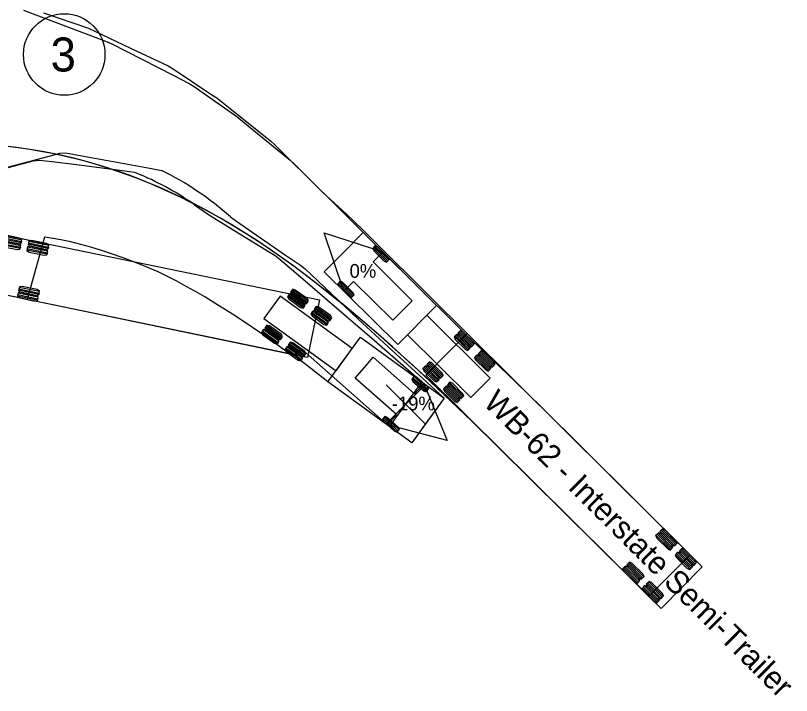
# Model space of a CAD drawing. Extents: x 1475900 to 1484331, y 375914 to 383395.
# Drawn here: x 1479059.2 to 1479171.7, y 379876.1 to 379974.6 of the extents above; entities that cross this region are included whole.
import ezdxf

# ---------------------------------------------------------------- set-up
doc = ezdxf.new("R2010")
doc.units = 0
doc.layers.add('0 (Construction)', color=7, linetype='Continuous')
doc.layers.add('Default', color=7, linetype='Continuous')

# ---------------------------------------------------------------- blocks, each defined once
blk = doc.blocks.new('ATRPTH_2')
at = {"layer": '0 (Construction)'}
blk.add_lwpolyline([(375840.717, 96487.897), (375840.359, 96487.536), (375838.916, 96488.967), (375838.559, 96488.607), (375837.832, 96490.759), (375839.99, 96490.049), (375839.632, 96489.688), (375841.074, 96488.257), (375840.717, 96487.897)], dxfattribs=at)
blk.add_circle((375828.26, 96497.315), 1.5, dxfattribs=at)
at = {"layer": 'Default'}
for points in [[(375850.233, 96476.932), (375844.254, 96482.859), (375843.255, 96483.836), (375842.499, 96484.564), (375841.737, 96485.285), (375841.097, 96485.879), (375840.448, 96486.466), (375839.926, 96486.929), (375839.396, 96487.387), (375838.86, 96487.839), (375838.045, 96488.503), (375837.501, 96488.93), (375837.082, 96489.248), (375836.66, 96489.561), (375836.098, 96489.961), (375835.531, 96490.347), (375834.953, 96490.721), (375834.513, 96490.991), (375834.07, 96491.253), (375833.471, 96491.586), (375833.172, 96491.745), (375832.87, 96491.899), (375832.563, 96492.049), (375831.941, 96492.34), (375831.478, 96492.542), (375831.021, 96492.727), (375830.552, 96492.903), (375829.912, 96493.122), (375829.433, 96493.269), (375829.113, 96493.362), (375828.629, 96493.488), (375828.304, 96493.566), (375827.815, 96493.671), (375827.324, 96493.763), (375826.995, 96493.817), (375826.668, 96493.866), (375826.173, 96493.928)], [(375827.498, 96498.848), (375829.15, 96498.284), (375830.705, 96497.543), (375832.088, 96496.895), (375832.273, 96496.784), (375833.694, 96495.836), (375833.873, 96495.718), (375834.369, 96495.323), (375835.861, 96494.135), (375836.015, 96493.993), (375837.775, 96492.252), (375838.651, 96491.438), (375839.253, 96490.863), (375839.846, 96490.281), (375851.754, 96478.465), (375850.233, 96476.932)], [(375849.782, 96477.38), (375844.185, 96482.927), (375843.153, 96483.935), (375842.268, 96484.786), (375841.535, 96485.476), (375840.942, 96486.023), (375840.344, 96486.563), (375839.746, 96487.089), (375839.145, 96487.604), (375838.535, 96488.111), (375838.072, 96488.485), (375837.615, 96488.846), (375837.172, 96489.186), (375836.721, 96489.521), (375836.264, 96489.85), (375835.801, 96490.171), (375835.336, 96490.481), (375834.885, 96490.77), (375834.427, 96491.051), (375833.961, 96491.322), (375833.489, 96491.585), (375833.016, 96491.834), (375832.549, 96492.067), (375832.234, 96492.216), (375831.755, 96492.431), (375831.269, 96492.635), (375830.789, 96492.823), (375830.309, 96492.997), (375829.822, 96493.159), (375829.33, 96493.308), (375828.843, 96493.442), (375828.515, 96493.523), (375828.018, 96493.635), (375827.516, 96493.735), (375827.009, 96493.821), (375826.5, 96493.894), (375825.988, 96493.953)], [(375826.762, 96498.95), (375829.168, 96498.042), (375829.776, 96497.81), (375829.984, 96497.725), (375832.273, 96496.554), (375832.858, 96496.252), (375833.042, 96496.135), (375834.616, 96495.035), (375835.107, 96494.634), (375836.581, 96493.423), (375836.737, 96493.277), (375843.048, 96487.019), (375844.022, 96486.096), (375844.876, 96485.271), (375845.844, 96484.324), (375847.312, 96482.873), (375851.303, 96478.912), (375849.782, 96477.38)], [(375839.269, 96490.765), (375841.973, 96488.081), (375840.542, 96486.639), (375837.837, 96489.322), (375838.553, 96490.043), (375839.269, 96490.765), (375839.269, 96490.765)], [(375839.63, 96490.191), (375840.135, 96489.69), (375840.171, 96489.726), (375839.666, 96490.227), (375839.702, 96490.263), (375840.207, 96489.762), (375840.219, 96489.775), (375840.179, 96489.861), (375839.801, 96490.237), (375839.714, 96490.275), (375839.618, 96490.179), (375839.658, 96490.093), (375840.036, 96489.717), (375840.123, 96489.678), (375840.219, 96489.775)], [(375838.342, 96488.893), (375838.847, 96488.392), (375838.883, 96488.428), (375838.378, 96488.929), (375838.414, 96488.965), (375838.918, 96488.464), (375838.93, 96488.476), (375838.891, 96488.563), (375838.512, 96488.939), (375838.426, 96488.977), (375838.33, 96488.881), (375838.369, 96488.795), (375838.748, 96488.419), (375838.835, 96488.38), (375838.93, 96488.476)], [(375840.9, 96486.999), (375843.226, 96484.691), (375843.941, 96485.412), (375841.615, 96487.72), (375840.9, 96486.999)], [(375842.767, 96487.078), (375843.272, 96486.577), (375843.308, 96486.613), (375842.803, 96487.114), (375842.839, 96487.15), (375843.344, 96486.649), (375843.356, 96486.661), (375843.316, 96486.748), (375842.938, 96487.124), (375842.851, 96487.162), (375842.755, 96487.066), (375842.795, 96486.98), (375843.173, 96486.604), (375843.26, 96486.565), (375843.356, 96486.661)], [(375843.1, 96487.053), (375851.754, 96478.465), (375850.993, 96477.698), (375850.233, 96476.932), (375841.579, 96485.52), (375842.339, 96486.286), (375843.1, 96487.053), (375843.1, 96487.053)], [(375842.624, 96486.934), (375843.129, 96486.433), (375843.165, 96486.469), (375842.66, 96486.97), (375842.696, 96487.006), (375843.201, 96486.505), (375843.212, 96486.517), (375843.173, 96486.604), (375842.795, 96486.98), (375842.708, 96487.018), (375842.612, 96486.922), (375842.651, 96486.835), (375843.03, 96486.46), (375843.117, 96486.421), (375843.212, 96486.517)], [(375843.525, 96486.327), (375844.029, 96485.826), (375844.065, 96485.862), (375843.56, 96486.363), (375843.596, 96486.399), (375844.101, 96485.898), (375844.113, 96485.91), (375844.074, 96485.997), (375843.695, 96486.372), (375843.608, 96486.411), (375843.513, 96486.315), (375843.552, 96486.228), (375843.93, 96485.852), (375844.017, 96485.814), (375844.113, 96485.91)], [(375841.622, 96485.924), (375842.127, 96485.423), (375842.163, 96485.459), (375841.658, 96485.96), (375841.694, 96485.996), (375842.199, 96485.496), (375842.211, 96485.508), (375842.171, 96485.594), (375841.793, 96485.97), (375841.706, 96486.008), (375841.61, 96485.912), (375841.65, 96485.826), (375842.028, 96485.45), (375842.115, 96485.411), (375842.211, 96485.508)], [(375843.381, 96486.183), (375843.886, 96485.682), (375843.922, 96485.718), (375843.417, 96486.219), (375843.453, 96486.255), (375843.958, 96485.754), (375843.97, 96485.766), (375843.93, 96485.852), (375843.552, 96486.228), (375843.465, 96486.267), (375843.369, 96486.171), (375843.409, 96486.084), (375843.787, 96485.708), (375843.874, 96485.67), (375843.97, 96485.766)], [(375841.479, 96485.78), (375841.984, 96485.279), (375842.02, 96485.315), (375841.515, 96485.816), (375841.551, 96485.852), (375842.056, 96485.351), (375842.067, 96485.363), (375842.028, 96485.45), (375841.65, 96485.826), (375841.563, 96485.864), (375841.467, 96485.768), (375841.506, 96485.681), (375841.885, 96485.306), (375841.972, 96485.267), (375842.067, 96485.363)], [(375842.379, 96485.173), (375842.884, 96484.672), (375842.92, 96484.708), (375842.415, 96485.209), (375842.451, 96485.245), (375842.956, 96484.744), (375842.968, 96484.756), (375842.929, 96484.843), (375842.55, 96485.218), (375842.463, 96485.257), (375842.368, 96485.161), (375842.407, 96485.074), (375842.785, 96484.699), (375842.872, 96484.66), (375842.968, 96484.756)], [(375842.236, 96485.029), (375842.741, 96484.528), (375842.777, 96484.564), (375842.272, 96485.065), (375842.308, 96485.101), (375842.813, 96484.6), (375842.825, 96484.612), (375842.785, 96484.699), (375842.407, 96485.074), (375842.32, 96485.113), (375842.224, 96485.017), (375842.264, 96484.93), (375842.642, 96484.554), (375842.729, 96484.516), (375842.825, 96484.612)], [(375850.047, 96479.626), (375850.584, 96479.093), (375850.622, 96479.132), (375850.086, 96479.664), (375850.124, 96479.702), (375850.66, 96479.17), (375850.673, 96479.183), (375850.631, 96479.275), (375850.229, 96479.674), (375850.136, 96479.715), (375850.035, 96479.613), (375850.077, 96479.521), (375850.479, 96479.122), (375850.571, 96479.081), (375850.673, 96479.183)], [(375850.2, 96479.779), (375850.736, 96479.247), (375850.774, 96479.285), (375850.238, 96479.817), (375850.276, 96479.855), (375850.812, 96479.323), (375850.825, 96479.336), (375850.783, 96479.428), (375850.381, 96479.827), (375850.288, 96479.868), (375850.187, 96479.766), (375850.229, 96479.674), (375850.631, 96479.275), (375850.723, 96479.234), (375850.825, 96479.336)], [(375850.921, 96479.063), (375851.457, 96478.531), (375851.495, 96478.569), (375850.959, 96479.102), (375850.997, 96479.14), (375851.533, 96478.608), (375851.546, 96478.62), (375851.504, 96478.712), (375851.102, 96479.112), (375851.009, 96479.153), (375850.908, 96479.05), (375850.95, 96478.958), (375851.352, 96478.559), (375851.444, 96478.518), (375851.546, 96478.62)], [(375850.769, 96478.91), (375851.305, 96478.378), (375851.343, 96478.416), (375850.807, 96478.948), (375850.845, 96478.987), (375851.381, 96478.454), (375851.394, 96478.467), (375851.352, 96478.559), (375850.95, 96478.958), (375850.857, 96478.999), (375850.756, 96478.897), (375850.798, 96478.805), (375851.2, 96478.406), (375851.292, 96478.365), (375851.394, 96478.467)], [(375848.983, 96478.553), (375849.519, 96478.021), (375849.557, 96478.059), (375849.021, 96478.591), (375849.059, 96478.63), (375849.595, 96478.097), (375849.608, 96478.11), (375849.566, 96478.202), (375849.164, 96478.601), (375849.072, 96478.642), (375848.97, 96478.54), (375849.012, 96478.448), (375849.414, 96478.049), (375849.507, 96478.008), (375849.608, 96478.11)], [(375848.831, 96478.4), (375849.367, 96477.867), (375849.405, 96477.906), (375848.869, 96478.438), (375848.907, 96478.476), (375849.443, 96477.944), (375849.456, 96477.957), (375849.414, 96478.049), (375849.012, 96478.448), (375848.92, 96478.489), (375848.818, 96478.387), (375848.86, 96478.295), (375849.262, 96477.896), (375849.355, 96477.855), (375849.456, 96477.957)], [(375849.552, 96477.684), (375850.088, 96477.152), (375850.126, 96477.19), (375849.59, 96477.722), (375849.628, 96477.761), (375850.164, 96477.228), (375850.177, 96477.241), (375850.135, 96477.333), (375849.733, 96477.732), (375849.641, 96477.773), (375849.539, 96477.671), (375849.581, 96477.579), (375849.983, 96477.18), (375850.076, 96477.139), (375850.177, 96477.241)], [(375849.704, 96477.837), (375850.24, 96477.305), (375850.279, 96477.343), (375849.742, 96477.876), (375849.78, 96477.914), (375850.317, 96477.382), (375850.329, 96477.394), (375850.288, 96477.486), (375849.885, 96477.886), (375849.793, 96477.927), (375849.691, 96477.824), (375849.733, 96477.732), (375850.135, 96477.333), (375850.228, 96477.292), (375850.329, 96477.394)]]:
    blk.add_lwpolyline(points, dxfattribs=at)
at = {"layer": '0 (Construction)'}
for s, height, p in [('3', 1.25, (375827.76, 96496.69)), ('0%', 0.508, (375838.766, 96489.099))]:
    blk.add_text(s, height=height, dxfattribs=at).set_placement(p)
at = {"layer": 'Default'}
blk.add_text('WB-62 - Interstate Semi-Trailer', height=0.83333, rotation=315.22, dxfattribs=at).set_placement((375843.652, 96484.456))
blk = doc.blocks.new('ATRPTH_5')
at = {"layer": '0 (Construction)'}
for p, q in [((375840.111, 96483.728), (375841.55, 96485.167)), ((375841.55, 96483.728), (375840.111, 96485.167))]:
    blk.add_line(p, q, dxfattribs=at)
blk.add_lwpolyline([(375839.302, 96485.792), (375839.638, 96486.173), (375841.163, 96484.831), (375841.499, 96485.212), (375842.354, 96483.107), (375840.157, 96483.687), (375840.492, 96484.068), (375838.967, 96485.41), (375839.302, 96485.792)], dxfattribs=at)
at = {"layer": 'Default'}
for points in [[(375788.045, 96481.255), (375816.115, 96490.274), (375817.509, 96490.706), (375819.106, 96491.189), (375820.021, 96491.467), (375820.221, 96491.529), (375821.108, 96491.779), (375822.513, 96492.181), (375823.299, 96492.399), (375823.849, 96492.547), (375824.855, 96492.829), (375827.891, 96493.626), (375828.093, 96493.68), (375828.309, 96493.696), (375831.41, 96493.128), (375831.842, 96493.051)], [(375788.649, 96481.449), (375808.09, 96487.694), (375810.477, 96488.449), (375812.624, 96489.117), (375814.229, 96489.606), (375818.261, 96490.901), (375819.254, 96491.219), (375823.883, 96492.539), (375827.117, 96493.403), (375827.346, 96493.429), (375827.811, 96493.377), (375828.906, 96493.24), (375830.205, 96493.068), (375830.85, 96492.98), (375831.083, 96492.886)], [(375833.059, 96491.785), (375833.607, 96491.398), (375834.543, 96490.829), (375835.839, 96490.028), (375836.023, 96489.914), (375836.205, 96489.777), (375837.049, 96489.063), (375838.205, 96488.072), (375839.667, 96486.805), (375841.432, 96485.266), (375840.224, 96483.633), (375838.086, 96485.518), (375837.033, 96486.454), (375836.654, 96486.222), (375835.998, 96486.701), (375835.458, 96487.082), (375834.956, 96487.426), (375834.452, 96487.76), (375833.944, 96488.083), (375833.434, 96488.394), (375833.092, 96488.593), (375832.748, 96488.785), (375832.404, 96488.97), (375832.059, 96489.146), (375831.713, 96489.313), (375831.366, 96489.471), (375831.193, 96489.545), (375830.791, 96489.704), (375830.43, 96489.839), (375829.969, 96489.998), (375829.601, 96490.117), (375829.234, 96490.227), (375828.867, 96490.327), (375828.503, 96490.417), (375828.141, 96490.494), (375827.783, 96490.56), (375827.536, 96490.592), (375826.898, 96488.298), (375826.372, 96488.413)], [(375834.381, 96491.344), (375834.565, 96491.203), (375836.411, 96489.938), (375836.956, 96489.568), (375837.128, 96489.424), (375839.076, 96487.591), (375840.192, 96486.555), (375841.458, 96485.393), (375842.247, 96484.676), (375841.054, 96483.031), (375837.97, 96485.268), (375837.169, 96485.892), (375836.688, 96486.26), (375826.126, 96488.456)], [(375837.223, 96486.172), (375825.281, 96488.632), (375825.499, 96489.689), (375825.717, 96490.746), (375837.658, 96488.287), (375837.44, 96487.23), (375837.223, 96486.172), (375837.223, 96486.172)], [(375826.698, 96490.489), (375825.958, 96490.641), (375825.947, 96490.589), (375826.687, 96490.436), (375826.676, 96490.383), (375825.936, 96490.536), (375825.932, 96490.518), (375826.018, 96490.464), (375826.573, 96490.349), (375826.673, 96490.366), (375826.702, 96490.507), (375826.616, 96490.561), (375826.061, 96490.675), (375825.961, 96490.659), (375825.932, 96490.518)], [(375826.654, 96490.277), (375825.914, 96490.43), (375825.903, 96490.377), (375826.644, 96490.225), (375826.633, 96490.172), (375825.893, 96490.324), (375825.889, 96490.307), (375825.974, 96490.252), (375826.529, 96490.138), (375826.629, 96490.154), (375826.658, 96490.295), (375826.573, 96490.349), (375826.018, 96490.464), (375825.918, 96490.448), (375825.889, 96490.307)], [(375827.693, 96490.284), (375826.953, 96490.436), (375826.942, 96490.384), (375827.682, 96490.231), (375827.671, 96490.178), (375826.931, 96490.331), (375826.928, 96490.313), (375827.013, 96490.259), (375827.568, 96490.144), (375827.668, 96490.161), (375827.697, 96490.302), (375827.611, 96490.356), (375827.056, 96490.47), (375826.957, 96490.454), (375826.928, 96490.313)], [(375827.65, 96490.073), (375826.909, 96490.225), (375826.899, 96490.172), (375827.639, 96490.02), (375827.628, 96489.967), (375826.888, 96490.119), (375826.884, 96490.102), (375826.969, 96490.047), (375827.524, 96489.933), (375827.624, 96489.949), (375827.653, 96490.09), (375827.568, 96490.144), (375827.013, 96490.259), (375826.913, 96490.243), (375826.884, 96490.102)], [(375827.301, 96488.381), (375826.561, 96488.533), (375826.55, 96488.48), (375827.29, 96488.328), (375827.279, 96488.275), (375826.539, 96488.428), (375826.536, 96488.41), (375826.621, 96488.356), (375827.176, 96488.241), (375827.276, 96488.257), (375827.305, 96488.398), (375827.219, 96488.453), (375826.664, 96488.567), (375826.565, 96488.551), (375826.536, 96488.41)], [(375827.345, 96488.592), (375826.605, 96488.745), (375826.594, 96488.692), (375827.334, 96488.539), (375827.323, 96488.487), (375826.583, 96488.639), (375826.579, 96488.621), (375826.664, 96488.567), (375827.219, 96488.453), (375827.319, 96488.469), (375827.348, 96488.61), (375827.263, 96488.664), (375826.708, 96488.779), (375826.608, 96488.762), (375826.579, 96488.621)], [(375837.241, 96488.243), (375836.665, 96488.661), (375836.636, 96488.62), (375837.211, 96488.202), (375837.182, 96488.161), (375836.606, 96488.579), (375836.596, 96488.565), (375836.648, 96488.485), (375837.08, 96488.172), (375837.172, 96488.147), (375837.251, 96488.257), (375837.199, 96488.337), (375836.767, 96488.65), (375836.675, 96488.675), (375836.596, 96488.565)], [(375838.864, 96486.501), (375836.212, 96488.425), (375835.615, 96487.603), (375838.268, 96485.679), (375838.864, 96486.501)], [(375837.122, 96488.079), (375836.546, 96488.496), (375836.516, 96488.455), (375837.092, 96488.038), (375837.062, 96487.997), (375836.487, 96488.414), (375836.477, 96488.4), (375836.529, 96488.321), (375836.96, 96488.008), (375837.052, 96487.983), (375837.132, 96488.093), (375837.08, 96488.172), (375836.648, 96488.485), (375836.556, 96488.51), (375836.477, 96488.4)], [(375838.105, 96487.617), (375837.529, 96488.035), (375837.499, 96487.993), (375838.075, 96487.576), (375838.045, 96487.535), (375837.469, 96487.952), (375837.459, 96487.939), (375837.512, 96487.859), (375837.943, 96487.546), (375838.035, 96487.521), (375838.115, 96487.631), (375838.063, 96487.71), (375837.631, 96488.023), (375837.539, 96488.048), (375837.459, 96487.939)], [(375837.985, 96487.453), (375837.41, 96487.87), (375837.38, 96487.829), (375837.956, 96487.411), (375837.926, 96487.37), (375837.35, 96487.788), (375837.34, 96487.774), (375837.392, 96487.695), (375837.824, 96487.381), (375837.916, 96487.357), (375837.995, 96487.466), (375837.943, 96487.546), (375837.512, 96487.859), (375837.42, 96487.884), (375837.34, 96487.774)], [(375836.168, 96486.763), (375835.592, 96487.18), (375835.562, 96487.139), (375836.138, 96486.722), (375836.108, 96486.681), (375835.532, 96487.098), (375835.522, 96487.085), (375835.574, 96487.005), (375836.006, 96486.692), (375836.098, 96486.667), (375836.177, 96486.777), (375836.125, 96486.856), (375835.694, 96487.169), (375835.602, 96487.194), (375835.522, 96487.085)], [(375836.287, 96486.927), (375835.711, 96487.345), (375835.681, 96487.304), (375836.257, 96486.886), (375836.227, 96486.845), (375835.651, 96487.263), (375835.641, 96487.249), (375835.694, 96487.169), (375836.125, 96486.856), (375836.217, 96486.831), (375836.297, 96486.941), (375836.245, 96487.021), (375835.813, 96487.334), (375835.721, 96487.359), (375835.641, 96487.249)], [(375841.054, 96483.031), (375837.97, 96485.268), (375839.163, 96486.913), (375842.247, 96484.676), (375841.65, 96483.853), (375841.054, 96483.031), (375841.054, 96483.031)], [(375837.031, 96486.137), (375836.455, 96486.554), (375836.426, 96486.513), (375837.001, 96486.095), (375836.971, 96486.054), (375836.396, 96486.472), (375836.386, 96486.458), (375836.438, 96486.379), (375836.87, 96486.065), (375836.961, 96486.041), (375837.041, 96486.15), (375836.989, 96486.23), (375836.557, 96486.543), (375836.465, 96486.568), (375836.386, 96486.458)], [(375837.15, 96486.301), (375836.575, 96486.719), (375836.545, 96486.678), (375837.121, 96486.26), (375837.091, 96486.219), (375836.515, 96486.636), (375836.505, 96486.623), (375836.557, 96486.543), (375836.989, 96486.23), (375837.081, 96486.205), (375837.16, 96486.315), (375837.108, 96486.394), (375836.676, 96486.708), (375836.585, 96486.732), (375836.505, 96486.623)], [(375841.666, 96484.994), (375841.131, 96485.463), (375841.097, 96485.424), (375841.632, 96484.955), (375841.599, 96484.917), (375841.064, 96485.386), (375841.053, 96485.373), (375841.097, 96485.289), (375841.498, 96484.938), (375841.588, 96484.904), (375841.677, 96485.006), (375841.632, 96485.09), (375841.231, 96485.442), (375841.142, 96485.475), (375841.053, 96485.373)], [(375840.591, 96483.512), (375840.058, 96483.983), (375840.024, 96483.945), (375840.558, 96483.474), (375840.524, 96483.436), (375839.991, 96483.907), (375839.98, 96483.894), (375840.024, 96483.81), (375840.424, 96483.457), (375840.513, 96483.423), (375840.603, 96483.525), (375840.558, 96483.609), (375840.158, 96483.962), (375840.069, 96483.996), (375839.98, 96483.894)]]:
    blk.add_lwpolyline(points, dxfattribs=at)
for radius, start, end in [(11.328, 55.1469, 66.6094), (11.798, 48.6404, 63.5416)]:
    blk.add_arc((375826.586, 96482.489), radius, start, end, dxfattribs=at)
at = {"layer": '0 (Construction)'}
blk.add_text('-19%', height=0.508, dxfattribs=at).set_placement((375840.32, 96484.221))

msp = doc.modelspace()

# ---------------------------------------------------------------- block references
at = {"layer": 'Default', "xscale": 3.937007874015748, "yscale": 3.937007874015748}
for name in ['ATRPTH_2', 'ATRPTH_5']:
    msp.add_blockref(name, (-572.52, 58.24), dxfattribs=at)

doc.saveas('drawing.dxf')
